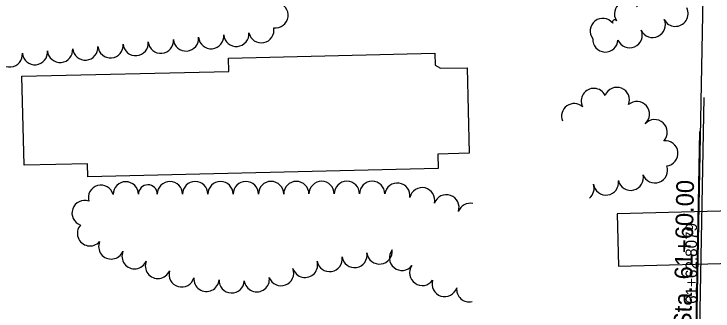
# Model space of a CAD drawing. Extents: x -25029 to 2274964, y -81170 to 687028.
# Drawn here: x -11332 to -10779, y -65868 to -65633 of the extents above; entities that cross this region are included whole.
import ezdxf

# ---------------------------------------------------------------- set-up
doc = ezdxf.new("R2010")
doc.units = 0
for name, color, linetype in [('BD_X_Canopy', 7, 'Continuous'), ('BLDG', 7, 'Continuous'), ('GE_X_CL_100', 7, 'Continuous'), ('SC_Scratch18', 7, 'Continuous'), ('TREES', 7, 'Continuous')]:
    doc.layers.add(name, color=color, linetype=linetype)

msp = doc.modelspace()

# ---------------------------------------------------------------- linework, layer by layer
at = {"layer": 'BD_X_Canopy'}
msp.add_line((-10785.12, -65528.96), (-10794.25, -65991.68), dxfattribs=at)
at = {"layer": 'BLDG'}
for points in [[(-11273.74, -65751.39), (-11324, -65752.58), (-11325.67, -65682.22), (-11162.02, -65678.34), (-11162.27, -65667.85), (-10999.08, -65663.98), (-10998.85, -65673.5), (-10994.43, -65675.93), (-10973.53, -65675.43), (-10971.93, -65743.1), (-10996.6, -65743.68), (-10996.33, -65755.06), (-11273.5, -65761.63)], [(-10853.67, -65832.24), (-10752.71, -65829.63), (-10752.38, -65842.35), (-10692.98, -65840.81), (-10694.56, -65779.81), (-10753.22, -65781.32), (-10753.04, -65788.39), (-10854.73, -65791.02)]]:
    msp.add_lwpolyline(points, close=True, dxfattribs=at)
at = {"layer": 'GE_X_CL_100'}
msp.add_line((-10794.16, -65986.68), (-10789.26, -65725.77), dxfattribs=at)
at = {"layer": 'SC_Scratch18'}
msp.add_line((-10791.43, -65991.73), (-10785.86, -65698.92), dxfattribs=at)
at = {"layer": 'TREES'}
for centre, radius, start, end in [((-11125.1, -65633.96), 10, 261.8662, 81.8662), ((-10846.92, -65632.83), 10, 33.3288, 213.3288), ((-10808.68, -65632.78), 10, 207.1723, 27.1723), ((-10866.21, -65646.44), 10, 37.8756, 217.8756), ((-10856.8, -65639.32), 1.81, 32.9677, 212.9677), ((-10826.63, -65641.59), 10, 205.1176, 25.1176), ((-11136.32, -65645.83), 10, 191.3493, 11.3493), ((-11156.09, -65648.7), 10, 185.1734, 5.1734), ((-10844.91, -65649.71), 10, 202.771, 22.771), ((-11215.84, -65654.11), 10, 185.1734, 5.1734), ((-11195.92, -65652.31), 10, 185.1734, 5.1734), ((-11176.01, -65650.5), 10, 185.1734, 5.1734), ((-10864.12, -65653.08), 10, 177.1518, 357.1518), ((-11295.52, -65661.33), 10, 185.1734, 5.1734), ((-11275.6, -65659.52), 10, 185.1734, 5.1734), ((-11255.68, -65657.72), 10, 185.1734, 5.1734), ((-11235.76, -65655.91), 10, 185.1734, 5.1734), ((-11335.35, -65664.93), 10, 185.1734, 5.1734), ((-11315.43, -65663.13), 10, 185.1734, 5.1734), ((-10873.25, -65701.78), 10, 26.68, 206.68), ((-10855.01, -65700.97), 10, 338.4082, 158.4082), ((-10888.78, -65713.78), 10, 48.7024, 201.8712), ((-10839.15, -65712.19), 10, 311, 131), ((-10825.19, -65726.46), 10, 317.7581, 137.7581), ((-10816.67, -65743.12), 10, 276.3903, 96.3903), ((-10824.94, -65756.53), 10, 200.3105, 20.3105), ((-10844.04, -65762.36), 10, 193.5989, 13.5989), ((-11243.54, -65775.54), 10, 0.3218, 180.3218), ((-11208.61, -65775.39), 10, 0.0793, 180.0793), ((-11188.61, -65775.36), 10, 0.0793, 180.0793), ((-11168.61, -65775.33), 10, 0.0793, 180.0793), ((-11148.61, -65775.31), 10, 0.0793, 180.0793), ((-11128.61, -65775.28), 10, 0.0793, 180.0793), ((-11108.61, -65775.25), 10, 0.0793, 180.0793), ((-11088.61, -65775.22), 10, 0.0793, 180.0793), ((-11068.61, -65775.2), 10, 0.0793, 180.0793), ((-11048.61, -65775.17), 10, 0.0793, 180.0793), ((-10863.66, -65766.12), 10, 188.0937, 8.0937), ((-11263.18, -65778.27), 10, 15.5094, 195.5094), ((-11226.08, -65775.45), 7.47, 0.3218, 180.3218), ((-11028.71, -65776.54), 10, 352.0127, 172.0127), ((-11009.07, -65780.23), 10, 346.73, 166.73), ((-10883.02, -65770.77), 10, 309.6152, 18.9378), ((-10989.89, -65785.8), 10, 340.8867, 160.8867), ((-11276.15, -65790.37), 10, 70.4846, 250.4846), ((-10971.06, -65792.54), 10, 77.4689, 159.7157), ((-11271.9, -65806.3), 10, 139.434, 319.434), ((-11255.07, -65816.65), 10, 157.3817, 337.3817), ((-11236.61, -65824.34), 10, 157.3817, 337.3817), ((-11042.78, -65820.61), 10, 186.9424, 6.9424), ((-11025.03, -65825.63), 10, 141.4967, 321.4967), ((-11082.32, -65826.62), 10, 189.1982, 9.1982), ((-11062.58, -65823.42), 10, 189.1982, 9.1982), ((-11218.15, -65832.04), 10, 157.3817, 337.3817), ((-11101.73, -65831.22), 10, 197.486, 17.4861), ((-11009, -65837.58), 10, 145.0956, 325.0956), ((-11199.33, -65838.72), 10, 163.5245, 343.5245), ((-11120.63, -65837.75), 10, 200.6147, 20.6147), ((-11179.76, -65842.27), 10, 175.8684, 355.8684), ((-11159.8, -65843.47), 10, 177.293, 357.293), ((-11139.9, -65842.6), 10, 187.6719, 7.6719), ((-10991.27, -65846.33), 10, 162.3871, 342.3871), ((-10971.81, -65850.55), 10, 173.1267, 283.077)]:
    msp.add_arc(centre, radius, start, end, dxfattribs=at)

# ---------------------------------------------------------------- texts
at = {"layer": 'GE_X_CL_100'}
msp.add_text('POT Sta. 61+60.00', height=14, rotation=88.9256, dxfattribs=at).set_placement((-10796.93, -65925.04))
at = {"layer": 'SC_Scratch18'}
msp.add_text('61+62.8079', height=9, rotation=90, dxfattribs=at).set_placement((-10791.64, -65862.08))

doc.saveas('drawing.dxf')
